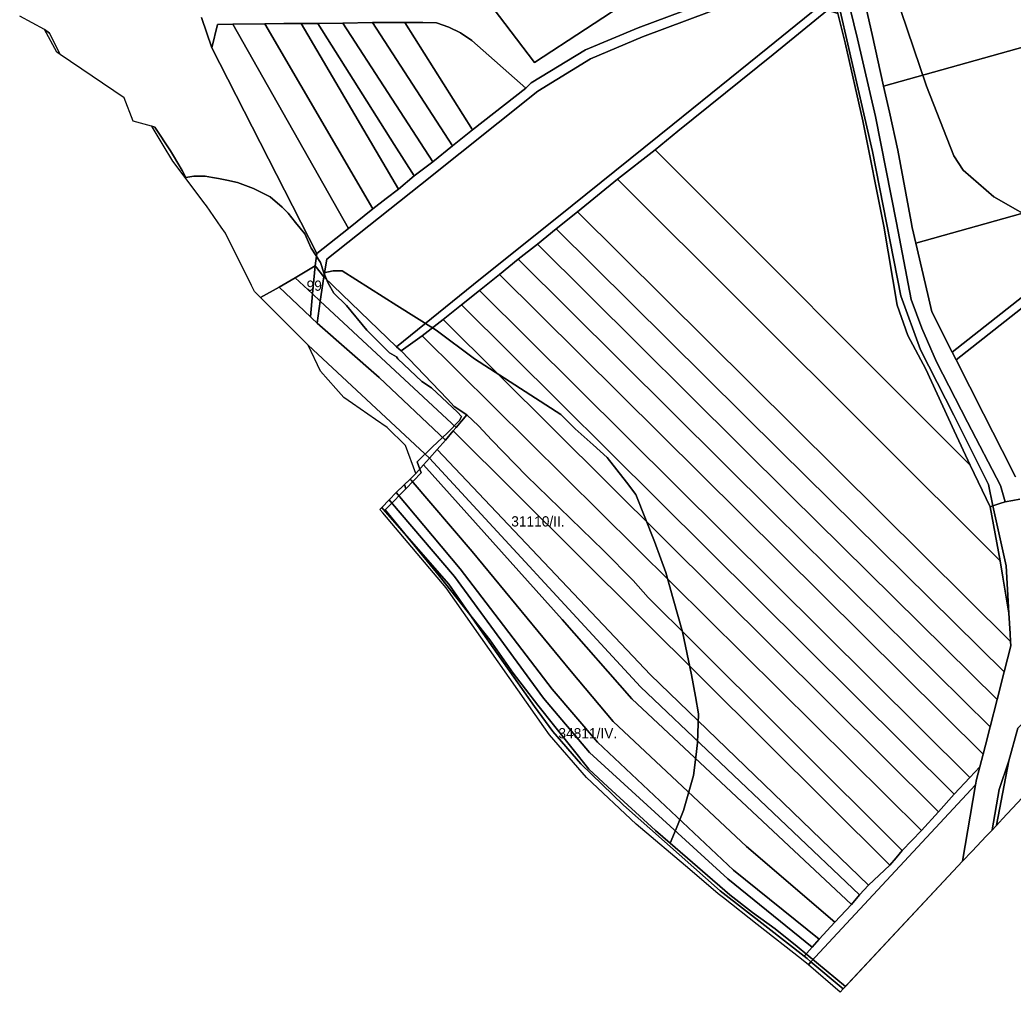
# Model space of a CAD drawing. Extents: x -541351 to -537540, y -1162694 to -1159725.
# Drawn here: x -539621.4 to -539137.5, y -1162407.6 to -1161933.8 of the extents above; entities that cross this region are included whole.
import ezdxf

# ---------------------------------------------------------------- set-up
doc = ezdxf.new("R2010")
doc.units = 0
for name, color, linetype in [('95560013', 7, 'Continuous'), ('95600013', 7, 'Continuous'), ('95610013', 7, 'Continuous'), ('95620013', 7, 'Continuous'), ('95630013', 7, 'Continuous'), ('95640013', 7, 'Continuous'), ('95660013', 7, 'Continuous')]:
    doc.layers.add(name, color=color, linetype=linetype)

msp = doc.modelspace()

# ---------------------------------------------------------------- linework, layer by layer
at = {"layer": '95560013'}
for points in [[(-539212.32, -1161913.69), (-539214.84, -1161903.7), (-539217.45, -1161893.33), (-539017.01, -1161837.1), (-539013.85, -1161913.55), (-539200.6, -1161966.02), (-539206.22, -1161940.94)], [(-539343.33, -1161952.72), (-539318.07, -1161942.05), (-539263.6, -1161921.58), (-539297.23, -1161851.16), (-539252.92, -1161883.34), (-539230.64, -1161899.55), (-539228.65, -1161907.73), (-539225.42, -1161921.81), (-539256.95, -1161947.48), (-539303.31, -1161984.78), (-539352.24, -1162024.23), (-539400.34, -1162062.78), (-539437.95, -1162093.1), (-539473.3, -1162058.96), (-539471.82, -1162050.32), (-539426.23, -1162014.21), (-539369.01, -1161968.59)], [(-539197.76, -1161978.7), (-539200.6, -1161966.02), (-539013.85, -1161913.55), (-539010.53, -1161993.75), (-539184.9, -1162042.56), (-539186.67, -1162034.94), (-539187.18, -1162032.19), (-539193.59, -1161997.34)], [(-539300.91, -1161987.96), (-539311.92, -1161997.05), (-539330.17, -1162011.43), (-539349.64, -1162027.3), (-539360.06, -1162035.62), (-539369.27, -1162043.08), (-539378.58, -1162050.4), (-539387.72, -1162057.87), (-539397.54, -1162065.69), (-539406.31, -1162072.59), (-539415.18, -1162079.79), (-539425.38, -1162087.75), (-539435.62, -1162095.01), (-539437.95, -1162093.1), (-539400.34, -1162062.78), (-539352.24, -1162024.23), (-539303.31, -1161984.78), (-539256.95, -1161947.48), (-539225.42, -1161921.81), (-539222.91, -1161930.72), (-539227.91, -1161929.12), (-539254.38, -1161950.7)], [(-539210.77, -1161982.93), (-539200.52, -1162034.32), (-539194.04, -1162072.72), (-539188.8, -1162087.6), (-539180.01, -1162104.01), (-539166.2, -1162134.06), (-539158.34, -1162150.83), (-539311.92, -1161997.05), (-539300.91, -1161987.96), (-539254.38, -1161950.7), (-539227.91, -1161929.12), (-539222.91, -1161930.72), (-539219.35, -1161944.98)], [(-539449.54, -1161935.07), (-539410.64, -1161995.17), (-539420.27, -1162002.87), (-539464.07, -1161935.33)], [(-539410.64, -1161995.17), (-539449.54, -1161935.07), (-539433.92, -1161935.07), (-539400.94, -1161987.38)], [(-539412.35, -1161937.32), (-539406.74, -1161940.17), (-539401.27, -1161943.89), (-539374.96, -1161966.99), (-539400.94, -1161987.38), (-539433.92, -1161935.07), (-539425.03, -1161934.99), (-539418.47, -1161935.25)], [(-539525.11, -1161936.11), (-539517.61, -1161935.85), (-539461.23, -1162035.39), (-539476.71, -1162047.7), (-539527.87, -1161947.38)], [(-539449.49, -1162025.9), (-539461.23, -1162035.39), (-539517.61, -1161935.85), (-539502.12, -1161935.76)], [(-539443.01, -1162020.87), (-539449.49, -1162025.9), (-539502.12, -1161935.76), (-539492.78, -1161935.62), (-539484.34, -1161935.5), (-539436.97, -1162016.19)], [(-539429.35, -1162009.81), (-539436.97, -1162016.19), (-539484.34, -1161935.5), (-539476.15, -1161935.5), (-539439.03, -1161994.45)], [(-539439.03, -1161994.45), (-539476.15, -1161935.5), (-539464.07, -1161935.33), (-539420.27, -1162002.87), (-539429.35, -1162009.81)], [(-539083.65, -1162052.18), (-539132.72, -1162068.62), (-539167.17, -1162095.62), (-539177.1, -1162076.06), (-539179.07, -1162067.59), (-539184.9, -1162042.56), (-539010.53, -1161993.75), (-539008.56, -1161993.2), (-539006.92, -1162037.12), (-539013.92, -1162037.13), (-539045.95, -1162041.27)], [(-539143.8, -1162197.43), (-539330.17, -1162011.43), (-539311.92, -1161997.05), (-539158.34, -1162150.83), (-539148.72, -1162171)], [(-539330.17, -1162011.43), (-539143.8, -1162197.43), (-539142.44, -1162205.39), (-539139.57, -1162222.82), (-539138.99, -1162232.85), (-539138.77, -1162236.64), (-539349.64, -1162027.3)], [(-539141.87, -1162251.48), (-539250.95, -1162143.7), (-539360.06, -1162035.62), (-539349.64, -1162027.3), (-539138.77, -1162236.64), (-539138.64, -1162238.84)], [(-539369.27, -1162043.08), (-539360.06, -1162035.62), (-539250.95, -1162143.7), (-539141.87, -1162251.48), (-539145.31, -1162264.9), (-539245.92, -1162165.53)], [(-539378.58, -1162050.4), (-539369.27, -1162043.08), (-539245.92, -1162165.53), (-539145.31, -1162264.9), (-539148.72, -1162278.22), (-539253.86, -1162174.39)], [(-539387.72, -1162057.87), (-539378.58, -1162050.4), (-539253.86, -1162174.39), (-539148.72, -1162278.22), (-539151, -1162287.13), (-539152.14, -1162291.59)], [(-539153.63, -1162297.71), (-539158.55, -1162302.95), (-539397.54, -1162065.69), (-539387.72, -1162057.87), (-539152.14, -1162291.59)], [(-539397.54, -1162065.69), (-539158.55, -1162302.95), (-539166.2, -1162311.1), (-539406.31, -1162072.59)], [(-539166.2, -1162311.1), (-539173.85, -1162319.61), (-539415.18, -1162079.79), (-539406.31, -1162072.59)], [(-539374.57, -1162155.96), (-539391.45, -1162138.61), (-539397.87, -1162131.59), (-539403.59, -1162126.17), (-539409.81, -1162122.16), (-539412.98, -1162118.53), (-539435.62, -1162095.01), (-539425.38, -1162087.75), (-539182.12, -1162328.86), (-539191.6, -1162338.47), (-539298.17, -1162232.21), (-539310.7, -1162219.78), (-539315.26, -1162215.17), (-539322.64, -1162206.96), (-539336.99, -1162192.33)], [(-539207.87, -1162355.46), (-539314.22, -1162252.89), (-539418.02, -1162143.08), (-539414.01, -1162138.54), (-539410.3, -1162134.11), (-539197.56, -1162345.65)], [(-539418.02, -1162143.08), (-539314.22, -1162252.89), (-539207.87, -1162355.46), (-539212.25, -1162360.2), (-539319.05, -1162258.85), (-539421.79, -1162147.32)], [(-539216.26, -1162364.82), (-539323.32, -1162264.69), (-539357.12, -1162225.97), (-539424.8, -1162150.56), (-539421.79, -1162147.32), (-539319.05, -1162258.85), (-539212.25, -1162360.2)], [(-539267.41, -1162336.61), (-539332.26, -1162275.65), (-539352.79, -1162251.24), (-539401.11, -1162192.84), (-539430.73, -1162158.06), (-539431.19, -1162157.52), (-539428.42, -1162154.88), (-539424.8, -1162150.56), (-539357.12, -1162225.97), (-539323.32, -1162264.69), (-539216.26, -1162364.82), (-539224.37, -1162373.53)], [(-539352.79, -1162251.24), (-539332.26, -1162275.65), (-539267.41, -1162336.61), (-539224.37, -1162373.53), (-539231.91, -1162381.68), (-539273.67, -1162348.07), (-539339.89, -1162285.73), (-539362.1, -1162259.92), (-539406.94, -1162201.22), (-539438.02, -1162164.06), (-539431.19, -1162157.52), (-539430.73, -1162158.06), (-539401.11, -1162192.84)], [(-539343.92, -1162290.72), (-539366.34, -1162264.27), (-539409.59, -1162204.94), (-539440.86, -1162168.46), (-539441.51, -1162167.71), (-539438.02, -1162164.06), (-539406.94, -1162201.22), (-539362.1, -1162259.92), (-539339.89, -1162285.73), (-539273.67, -1162348.07), (-539231.91, -1162381.68), (-539235.31, -1162385.58), (-539276.53, -1162352.31)], [(-539256.91, -1162376.17), (-539280.14, -1162358.21), (-539327.3, -1162316.45), (-539348.13, -1162296.3), (-539361.69, -1162280.54), (-539370.74, -1162268.42), (-539395.83, -1162232.7), (-539412.38, -1162208.76), (-539444.47, -1162172.16), (-539445.09, -1162171.46), (-539441.51, -1162167.71), (-539440.86, -1162168.46), (-539409.59, -1162204.94), (-539366.34, -1162264.27), (-539343.92, -1162290.72), (-539276.53, -1162352.31), (-539235.31, -1162385.58), (-539239.32, -1162390.08)], [(-539139.62, -1162294.87), (-539135.12, -1162278.84), (-539096.84, -1162239.12), (-539091, -1162240.09), (-539085.53, -1162249.94), (-539082.83, -1162259.23), (-539142.64, -1162323.16), (-539145.63, -1162326.35), (-539145.6, -1162326.2)], [(-539224.37, -1162373.53), (-539216.26, -1162364.82), (-539212.25, -1162360.2), (-539207.87, -1162355.46), (-539197.56, -1162345.65), (-539194.4, -1162342.12), (-539191.6, -1162338.47), (-539182.12, -1162328.86), (-539173.85, -1162319.61), (-539166.2, -1162311.1), (-539158.55, -1162302.95), (-539153.63, -1162297.71), (-539155.31, -1162303.99), (-539155.74, -1162306.54), (-539236.04, -1162392.75), (-539237.87, -1162391.17), (-539239.32, -1162390.08), (-539235.31, -1162385.58), (-539231.91, -1162381.68)], [(-539236.04, -1162392.75), (-539155.74, -1162306.54), (-539162.08, -1162343.72), (-539220.33, -1162405.99)]]:
    msp.add_lwpolyline(points, close=True, dxfattribs=at)
for points in [[(-539411.01, -1161901.38), (-539370.71, -1161954.54), (-539320.94, -1161921.88)], [(-539263.6, -1161921.58), (-539318.07, -1161942.05), (-539343.33, -1161952.72), (-539369.01, -1161968.59), (-539426.23, -1162014.21), (-539471.82, -1162050.32), (-539473.3, -1162058.96), (-539477.49, -1162053.65), (-539476.71, -1162047.7), (-539461.23, -1162035.39), (-539449.49, -1162025.9), (-539443.01, -1162020.87), (-539436.97, -1162016.19), (-539429.35, -1162009.81), (-539420.27, -1162002.87), (-539410.64, -1161995.17), (-539400.94, -1161987.38), (-539374.96, -1161966.99), (-539372.22, -1161964.47), (-539345.81, -1161948.42), (-539320.22, -1161937.6), (-539297.92, -1161929.45)], [(-539297.92, -1161929.45), (-539320.22, -1161937.6), (-539345.81, -1161948.42), (-539372.22, -1161964.47), (-539374.96, -1161966.99), (-539401.27, -1161943.89), (-539406.74, -1161940.17), (-539412.35, -1161937.32), (-539418.47, -1161935.25), (-539425.03, -1161934.99), (-539433.92, -1161935.07), (-539449.54, -1161935.07), (-539464.07, -1161935.33), (-539476.15, -1161935.5), (-539484.34, -1161935.5), (-539492.78, -1161935.62), (-539502.12, -1161935.76), (-539517.61, -1161935.85), (-539525.11, -1161936.11), (-539527.87, -1161947.38), (-539532.84, -1161932.62)], [(-539136.3, -1162156.43), (-539142.82, -1162143.59), (-539151.92, -1162125.67), (-539165.27, -1162099.36), (-539130.8, -1162072.28)]]:
    msp.add_lwpolyline(points, dxfattribs=at)
at = {"layer": '95600013'}
msp.add_lwpolyline([(-539416.41, -1161860.82), (-539434.71, -1161859.39), (-539434.97, -1161857.81), (-539448.61, -1161858.31), (-539471.15, -1161856.57), (-539490.37, -1161855.82), (-539472.81, -1161855.26), (-539469.96, -1161855.26), (-539435.74, -1161853.86), (-539404.93, -1161857.98), (-539391.68, -1161864.38), (-539379.32, -1161864.7), (-539364.84, -1161856.72), (-539349.38, -1161840.87), (-539345.14, -1161830.84), (-539334.65, -1161855.61), (-539327.48, -1161884.12), (-539320.94, -1161921.88), (-539370.71, -1161954.54), (-539411.01, -1161901.38)], close=True, dxfattribs=at)
at = {"layer": '95610013'}
for points in [[(-539477.49, -1162053.65), (-539478.8, -1162067.31), (-539487.26, -1162059.44)], [(-539478.8, -1162067.31), (-539477.49, -1162053.65), (-539473.3, -1162058.96), (-539475.02, -1162070.83)], [(-539408.87, -1162132.42), (-539475.02, -1162070.83), (-539473.3, -1162058.96), (-539437.95, -1162093.1), (-539435.62, -1162095.01), (-539412.98, -1162118.53), (-539409.81, -1162122.16), (-539403.59, -1162126.17)], [(-539415.18, -1162079.79), (-539173.85, -1162319.61), (-539182.12, -1162328.86), (-539425.38, -1162087.75)], [(-539336.99, -1162192.33), (-539322.64, -1162206.96), (-539315.26, -1162215.17), (-539310.7, -1162219.78), (-539298.17, -1162232.21), (-539191.6, -1162338.47), (-539194.4, -1162342.12), (-539197.56, -1162345.65), (-539410.3, -1162134.11), (-539408.87, -1162132.42), (-539403.59, -1162126.17), (-539397.87, -1162131.59), (-539391.45, -1162138.61), (-539374.57, -1162155.96)]]:
    msp.add_lwpolyline(points, close=True, dxfattribs=at)
at = {"layer": '95620013'}
msp.add_lwpolyline([(-539532.84, -1161932.62), (-539527.87, -1161947.38), (-539476.71, -1162047.7), (-539477.49, -1162053.65), (-539487.26, -1162059.44), (-539495, -1162064.02), (-539504.16, -1162068.99), (-539507.05, -1162066.09), (-539508.49, -1162063.21), (-539521.19, -1162037.78), (-539523.3, -1162034.76), (-539530.55, -1162024.39), (-539531.71, -1162022.73), (-539544.35, -1162006.01), (-539546.89, -1162002.65), (-539551.6, -1161994.82), (-539556.91, -1161985.97), (-539557.2, -1161985.49), (-539566.21, -1161983.21), (-539570.54, -1161971.78), (-539601.83, -1161950.6), (-539606.94, -1161940.24), (-539609.42, -1161938.46), (-539621.4, -1161931.95)], dxfattribs=at)
for points in [[(-539479.87, -1162078.42), (-539495, -1162064.02), (-539487.26, -1162059.44), (-539478.8, -1162067.31)], [(-539504.16, -1162068.99), (-539495, -1162064.02), (-539479.87, -1162078.42), (-539479.13, -1162079.08), (-539476.58, -1162081.54), (-539446.37, -1162108.1), (-539414.01, -1162138.54), (-539418.02, -1162143.08), (-539421.79, -1162147.32), (-539480.99, -1162092.24), (-539481.32, -1162091.91)], [(-539479.87, -1162078.42), (-539478.8, -1162067.31), (-539475.02, -1162070.83), (-539476.58, -1162081.54), (-539479.13, -1162079.08)], [(-539408.87, -1162132.42), (-539410.3, -1162134.11), (-539414.01, -1162138.54), (-539446.37, -1162108.1), (-539476.58, -1162081.54), (-539475.02, -1162070.83)], [(-539474.98, -1162104.91), (-539480.99, -1162092.24), (-539421.79, -1162147.32), (-539424.8, -1162150.56), (-539428.42, -1162154.88), (-539433.54, -1162141.24), (-539442.45, -1162132.43), (-539448.09, -1162128.53), (-539459.31, -1162120.75), (-539463.62, -1162117.77), (-539467.52, -1162113.35)]]:
    msp.add_lwpolyline(points, close=True, dxfattribs=at)
at = {"layer": '95630013'}
msp.add_lwpolyline([(-539601.83, -1161950.6), (-539603.32, -1161949.59), (-539609.42, -1161938.46), (-539606.94, -1161940.24)], close=True, dxfattribs=at)
at = {"layer": '95640013'}
for points in [[(-539166.43, -1162126.43), (-539182.54, -1162094.64), (-539192.18, -1162068.27), (-539206, -1161997.95), (-539224.46, -1161917.18), (-539246.32, -1161840.14), (-539256.35, -1161802.83), (-539251.17, -1161802.72), (-539248.53, -1161802.66), (-539238.86, -1161839.87), (-539230.73, -1161874.17), (-539222.37, -1161905.58), (-539213.27, -1161942.94), (-539204.57, -1161980.85), (-539194.37, -1162032.7), (-539187.23, -1162069.96), (-539181.96, -1162084.06), (-539174.75, -1162100.35), (-539159.66, -1162129.85), (-539143.64, -1162160.68), (-539141.34, -1162168.63), (-539143.95, -1162169.47), (-539147.29, -1162170.54), (-539149.55, -1162160.22)], [(-539180.01, -1162104.01), (-539188.8, -1162087.6), (-539194.04, -1162072.72), (-539200.52, -1162034.32), (-539210.77, -1161982.93), (-539219.35, -1161944.98), (-539222.91, -1161930.72), (-539225.42, -1161921.81), (-539228.65, -1161907.73), (-539230.64, -1161899.55), (-539234.16, -1161886.78), (-539246.32, -1161840.14), (-539224.46, -1161917.18), (-539206, -1161997.95), (-539192.18, -1162068.27), (-539182.54, -1162094.64), (-539166.43, -1162126.43), (-539149.55, -1162160.22), (-539147.29, -1162170.54), (-539148.72, -1162171), (-539158.34, -1162150.83), (-539166.2, -1162134.06)], [(-539239.32, -1162390.08), (-539237.87, -1162391.17), (-539236.04, -1162392.75), (-539237.22, -1162394.22), (-539240.64, -1162391.52), (-539262.13, -1162374.59), (-539278.66, -1162361.57), (-539281.12, -1162359.63), (-539295.02, -1162347.82), (-539321.09, -1162325.65), (-539345.26, -1162302.92), (-539363.42, -1162282.15), (-539366.13, -1162278.3), (-539405.31, -1162222.51), (-539413.74, -1162210.51), (-539444.53, -1162174.06), (-539445.96, -1162172.37), (-539445.09, -1162171.46), (-539444.47, -1162172.16), (-539412.38, -1162208.76), (-539395.83, -1162232.7), (-539370.74, -1162268.42), (-539361.69, -1162280.54), (-539348.13, -1162296.3), (-539327.3, -1162316.45), (-539280.14, -1162358.21), (-539256.91, -1162376.17)], [(-539147.29, -1162170.54), (-539140.9, -1162199.79), (-539139.57, -1162222.82), (-539142.44, -1162205.39), (-539143.8, -1162197.43), (-539148.72, -1162171)], [(-539144.23, -1162308.88), (-539139.62, -1162294.87), (-539145.6, -1162326.2), (-539145.63, -1162326.35), (-539145.93, -1162326.67), (-539147.73, -1162328.57), (-539147.7, -1162328.42)], [(-539236.04, -1162392.75), (-539220.33, -1162405.99), (-539221.79, -1162407.55), (-539237.22, -1162394.22)]]:
    msp.add_lwpolyline(points, close=True, dxfattribs=at)
for points in [[(-539134.14, -1162167.31), (-539137.66, -1162167.95), (-539141.34, -1162168.63), (-539143.64, -1162160.68), (-539159.66, -1162129.85), (-539174.75, -1162100.35), (-539181.96, -1162084.06), (-539187.23, -1162069.96), (-539194.37, -1162032.7), (-539204.57, -1161980.85), (-539213.27, -1161942.94), (-539222.37, -1161905.58)], [(-539212.32, -1161913.69), (-539206.22, -1161940.94), (-539200.6, -1161966.02), (-539197.76, -1161978.7), (-539193.59, -1161997.34), (-539187.18, -1162032.19), (-539186.67, -1162034.94), (-539184.9, -1162042.56), (-539179.07, -1162067.59), (-539177.1, -1162076.06), (-539167.17, -1162095.62), (-539165.27, -1162099.36), (-539151.92, -1162125.67), (-539142.82, -1162143.59), (-539136.3, -1162156.43)], [(-538869.43, -1162041.03), (-538875.54, -1162042.25), (-538907.04, -1162043.97), (-538925.8, -1162043.6), (-538939.77, -1162044.97), (-538989.46, -1162041.38), (-539013.66, -1162041.4), (-539045.11, -1162045.4), (-539082.49, -1162055.78), (-539130.8, -1162072.28), (-539165.27, -1162099.36), (-539167.17, -1162095.62), (-539132.72, -1162068.62), (-539083.65, -1162052.18), (-539045.95, -1162041.27), (-539013.92, -1162037.13), (-539006.92, -1162037.12), (-539003.92, -1162037.12), (-538989.17, -1162037.11), (-538941.77, -1162040.48), (-538926.62, -1162040.85), (-538876.72, -1162036.74), (-538865.57, -1162034.76)], [(-539135.12, -1162278.84), (-539139.62, -1162294.87), (-539144.23, -1162308.88), (-539147.7, -1162328.42), (-539147.73, -1162328.57), (-539149.02, -1162329.93), (-539150.57, -1162331.57), (-539157.48, -1162338.86), (-539162.08, -1162343.72), (-539155.74, -1162306.54), (-539155.31, -1162303.99), (-539153.63, -1162297.71), (-539152.14, -1162291.59), (-539151, -1162287.13), (-539148.72, -1162278.22), (-539145.31, -1162264.9), (-539141.87, -1162251.48), (-539138.64, -1162238.84), (-539138.77, -1162236.64), (-539138.99, -1162232.85), (-539139.57, -1162222.82), (-539140.9, -1162199.79), (-539147.29, -1162170.54), (-539143.95, -1162169.47), (-539141.34, -1162168.63), (-539137.66, -1162167.95), (-539134.14, -1162167.31)]]:
    msp.add_lwpolyline(points, dxfattribs=at)
at = {"layer": '95660013'}
for points in [[(-538849.37, -1162026), (-538883.31, -1162026), (-538901.69, -1162028), (-538909.81, -1162029), (-538924.12, -1162033), (-538942.12, -1162039), (-538952.69, -1162042), (-538970.62, -1162046), (-539003.31, -1162049), (-539026, -1162051), (-539042.81, -1162053), (-539068, -1162052), (-539087.37, -1162047), (-539110.81, -1162041), (-539122.37, -1162034), (-539146.81, -1162020), (-539161.87, -1162007), (-539166.31, -1162000), (-539179.62, -1161966), (-539195.31, -1161920)], [(-539195.31, -1161920), (-539179.62, -1161966), (-539166.31, -1162000), (-539161.87, -1162007), (-539146.81, -1162020), (-539122.37, -1162034), (-539110.81, -1162041), (-539087.37, -1162047), (-539068, -1162052), (-539042.81, -1162053), (-539026, -1162051), (-539003.31, -1162049), (-538970.62, -1162046), (-538952.69, -1162042), (-538942.12, -1162039), (-538924.12, -1162033), (-538909.81, -1162029), (-538901.69, -1162028), (-538883.31, -1162026), (-538849.37, -1162026)], [(-539082.83, -1162259.23), (-539142.64, -1162323.16), (-539145.63, -1162326.35), (-539145.93, -1162326.67), (-539147.73, -1162328.57), (-539149.02, -1162329.93), (-539150.57, -1162331.57), (-539157.48, -1162338.86), (-539162.08, -1162343.72), (-539219.15, -1162404.73), (-539242.75, -1162385.34), (-539253.38, -1162376.78), (-539264.51, -1162368.82), (-539275.57, -1162360.12), (-539304.5, -1162335.01), (-539301.67, -1162327.9), (-539298.12, -1162319), (-539293.12, -1162302), (-539292.05, -1162293.11), (-539291.19, -1162286), (-539290.69, -1162272), (-539292.21, -1162263.56), (-539294.12, -1162253), (-539298.62, -1162232), (-539303.1, -1162215.89), (-539306.69, -1162203), (-539309.1, -1162196.33), (-539312.12, -1162188), (-539321.37, -1162165), (-539325.81, -1162159), (-539335.19, -1162147), (-539342.16, -1162140.78), (-539350.87, -1162133), (-539357.81, -1162126), (-539399.87, -1162099), (-539418.62, -1162085), (-539437.81, -1162073), (-539464.31, -1162056), (-539468.69, -1162056), (-539473.31, -1162057), (-539474.87, -1162052), (-539479.5, -1162045), (-539482.62, -1162038), (-539487.1, -1162032.44), (-539490.69, -1162028), (-539491.99, -1162026.67), (-539493.62, -1162025), (-539499.37, -1162020), (-539507.5, -1162016), (-539515.37, -1162013), (-539520.55, -1162011.89), (-539524.69, -1162011), (-539527.55, -1162010.56), (-539531.12, -1162010), (-539536.69, -1162010), (-539540.49, -1162010.51), (-539542.26, -1162007.11), (-539546.54, -1162000), (-539547.96, -1161997.64), (-539555.71, -1161986.09), (-539557.11, -1161985.63), (-539557.2, -1161985.49), (-539566.21, -1161983.21), (-539570.54, -1161971.78), (-539601.83, -1161950.6), (-539603.32, -1161949.59), (-539609.42, -1161938.46), (-539621.4, -1161931.95)]]:
    msp.add_lwpolyline(points, dxfattribs=at)
for points in [[(-539542.26, -1162007.11), (-539540.49, -1162010.51), (-539536.69, -1162010), (-539531.12, -1162010), (-539527.55, -1162010.56), (-539524.69, -1162011), (-539520.55, -1162011.89), (-539515.37, -1162013), (-539507.5, -1162016), (-539499.37, -1162020), (-539493.62, -1162025), (-539491.99, -1162026.67), (-539490.69, -1162028), (-539487.1, -1162032.44), (-539482.62, -1162038), (-539479.5, -1162045), (-539474.87, -1162052), (-539473.31, -1162057), (-539471.12, -1162062), (-539468.37, -1162067), (-539462.31, -1162073), (-539452.31, -1162085), (-539441.31, -1162096), (-539437.87, -1162098), (-539437.31, -1162099), (-539425.62, -1162110), (-539420.81, -1162113), (-539408.12, -1162125), (-539406.31, -1162127), (-539407.19, -1162129), (-539413.12, -1162135), (-539420.46, -1162142.01), (-539427.87, -1162149.08), (-539425.88, -1162154.53), (-539433.33, -1162162.22), (-539434.03, -1162160.24), (-539431.19, -1162157.52), (-539428.42, -1162154.88), (-539433.54, -1162141.24), (-539442.45, -1162132.43), (-539448.09, -1162128.53), (-539459.31, -1162120.75), (-539463.62, -1162117.77), (-539467.52, -1162113.35), (-539474.98, -1162104.91), (-539480.99, -1162092.24), (-539481.32, -1162091.91), (-539504.16, -1162068.99), (-539507.05, -1162066.09), (-539508.49, -1162063.21), (-539521.19, -1162037.78), (-539523.3, -1162034.76), (-539530.55, -1162024.39), (-539531.71, -1162022.73), (-539544.35, -1162006.01), (-539546.89, -1162002.65), (-539551.6, -1161994.82), (-539556.91, -1161985.97), (-539557.11, -1161985.63), (-539555.71, -1161986.09), (-539547.96, -1161997.64), (-539546.54, -1162000)], [(-539304.5, -1162335.01), (-539311.65, -1162328.81), (-539334.92, -1162307.58), (-539344.14, -1162298.82), (-539369.1, -1162267.75), (-539381.1, -1162252.12), (-539392.49, -1162235.81), (-539416.95, -1162204.86), (-539443.4, -1162172.6), (-539441.92, -1162171.08), (-539433.33, -1162162.22), (-539425.88, -1162154.53), (-539427.87, -1162149.08), (-539420.46, -1162142.01), (-539413.12, -1162135), (-539407.19, -1162129), (-539406.31, -1162127), (-539408.12, -1162125), (-539420.81, -1162113), (-539425.62, -1162110), (-539437.31, -1162099), (-539437.87, -1162098), (-539441.31, -1162096), (-539452.31, -1162085), (-539462.31, -1162073), (-539468.37, -1162067), (-539471.12, -1162062), (-539473.31, -1162057), (-539468.69, -1162056), (-539464.31, -1162056), (-539437.81, -1162073), (-539418.62, -1162085), (-539399.87, -1162099), (-539357.81, -1162126), (-539350.87, -1162133), (-539342.16, -1162140.78), (-539335.19, -1162147), (-539325.81, -1162159), (-539321.37, -1162165), (-539312.12, -1162188), (-539309.1, -1162196.33), (-539306.69, -1162203), (-539303.1, -1162215.89), (-539298.62, -1162232), (-539294.12, -1162253), (-539292.21, -1162263.56), (-539290.69, -1162272), (-539291.19, -1162286), (-539292.05, -1162293.11), (-539293.12, -1162302), (-539298.12, -1162319), (-539301.67, -1162327.9)], [(-539220.33, -1162405.99), (-539221.79, -1162407.55), (-539237.22, -1162394.22), (-539240.64, -1162391.52), (-539262.13, -1162374.59), (-539278.66, -1162361.57), (-539281.12, -1162359.63), (-539295.02, -1162347.82), (-539321.09, -1162325.65), (-539345.26, -1162302.92), (-539363.42, -1162282.15), (-539366.13, -1162278.3), (-539405.31, -1162222.51), (-539413.74, -1162210.51), (-539444.53, -1162174.06), (-539445.96, -1162172.37), (-539445.09, -1162171.46), (-539441.51, -1162167.71), (-539438.02, -1162164.06), (-539434.03, -1162160.24), (-539433.33, -1162162.22), (-539441.92, -1162171.08), (-539443.4, -1162172.6), (-539416.95, -1162204.86), (-539392.49, -1162235.81), (-539381.1, -1162252.12), (-539369.1, -1162267.75), (-539344.14, -1162298.82), (-539334.92, -1162307.58), (-539311.65, -1162328.81), (-539304.5, -1162335.01), (-539275.57, -1162360.12), (-539264.51, -1162368.82), (-539253.38, -1162376.78), (-539242.75, -1162385.34), (-539219.15, -1162404.73)]]:
    msp.add_lwpolyline(points, close=True, dxfattribs=at)

# ---------------------------------------------------------------- texts
for s, rotation, p in [('99', 360, (-539481.71, -1162065.78)), ('31110/II.', 0, (-539382, -1162180.65)), ('34811/IV.', 360, (-539359.01, -1162283.9))]:
    msp.add_text(s, height=5, rotation=rotation, dxfattribs=at).set_placement(p)

doc.saveas('drawing.dxf')
